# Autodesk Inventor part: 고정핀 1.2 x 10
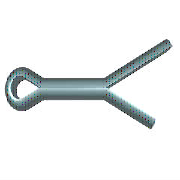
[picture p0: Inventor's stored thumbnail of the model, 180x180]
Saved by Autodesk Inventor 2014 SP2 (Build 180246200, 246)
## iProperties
IsCustomPart: 1
Created: 2012-02
Part Number: 고정핀 1.2 x 10
Material: 강철
Description: 분할 핀
Document SubType Name: Modeling
Standard: ISO 1234
Designer: test
Standard Revision: Second edition 1997-11-01
Standards Organization: ISO
Language: ko-KR
Size Designation: 1.2 x 10
Categories: <MemberInstance><Categories><Category DisplayName="조임쇠" InternalName="e4da775c-781d-43d5-af7c-5136215cf5a6" Mnemonic="FSTN"><Category DisplayName="핀" InternalNa
Density: 7.85 g/cm^3
Appearance: 강철
Author: test
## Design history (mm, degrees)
sketch "스케치1"
  geometry: L1 (0, 0.5)-(5, 0.5); L2 (0, -0.5)-(5, -0.5); L3 (5, 0.5)-(10, 2.416); L4 (10, 2.416)-(10.167, 1.98); L5 (10.167, 1.98)-(5, 0); L6 (5, 0)-(12.667, -2.937); L7 (12.667, -2.937)-(12.5, -3.373); L8 (12.5, -3.373)-(5, -0.5); L9 (0, 0)-(-1.875, -0.484); L10 (0, 0)-(-1.875, 0.484); L11 (0, 0.5)-(0, -0.5); L12 (0, 0.5)-(-1.742, 0.966); L13 (0, -0.5)-(-1.742, -0.966); L14 (-3, 0)-(5, 0); L15 (5, 0.5)-(5, -0.5); A1 r 1 centre (-2, 0) between (-1.742, 0.966) and (-1.742, -0.966); A2 r 0.5 centre (-2, 0) between (-1.875, 0.484) and (-1.875, -0.484); 1 further point
  constraints: 30 end point, 5 point on circle, 4 parallel, 4 perpendicular, 4 point on line, 4 tangent, 2 centre point, 2 midpoint, 1 coincident, 1 horizontal
  dimensions: "d0" = 5 distance of L1.start L1.end (= MSIAB); "d1" = 10 horizontal distance of L1.start L3.end (= SNLG); "d2" = 159.037 deg angle of L1 L3; "d3" = 159.037 deg angle of L2 L8; "d4" = 2.5 horizontal distance of L3.end L7.end (= LGDIF); "d5" = 0.5 radius of A2 (= -0.5 x SNND1 + 0.5 x KBR); "d6" = 1 radius of A1 (= 0.5 x KBR); "d7" = 0.5 distance from line of L1 L9.start (= 0.5 x SNND1); "d8" = 0.5 distance between parallel lines of L2 L14 (= 0.5 x SNND1); "d9" = 2 distance from line of L11 A1.centre (= KOL - 0.5 x KBR)
extrude "본체" new body sketch "스케치1" stored distance "d10" = 1 (= SNND1); taper "d11" = 0 deg
workaxis "Work Axis1"
workplane "Work Plane1"
workplane "Work Plane3"
body "Solid1"
fillet "모깎기" dims "d12" = 0.35 (= 0.35 x SNND1)
other parameters: "SNND" = 1.2 [user parameter], "SNLG" = 10 [user parameter; used in 1 equation term], "SNND1" = 1 [user parameter; used in 5 equation terms], "KBR" = 2 [user parameter; used in 3 equation terms], "KOL" = 3 [user parameter; used in 1 equation term], "LGDIF" = 2.5 [user parameter; used in 1 equation term], "MSIAB" = 5 [user parameter; used in 1 equation term], "d15" = 0, "d16" = 0, "d17" = 0, "NNDMAX" = 5.5 [user parameter], "DSH" = 2.6 [user parameter], "NNDMIN" = 4.5 [user parameter]
